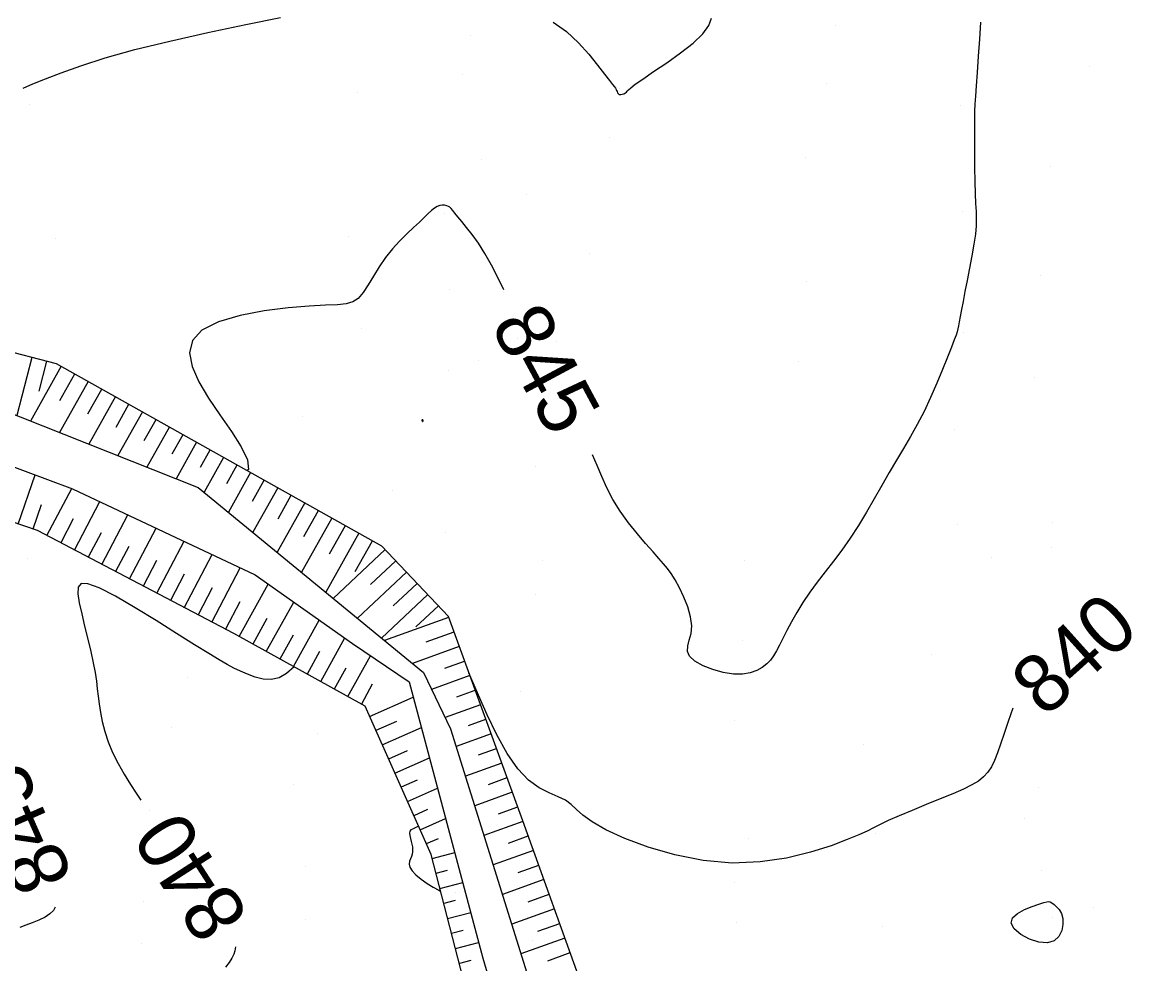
# Model space of a CAD drawing. Extents: x 400243 to 403697, y 4403637 to 4408083.
# Drawn here: x 402954.4 to 403097.6, y 4406092.9 to 4406214.4 of the extents above; entities that cross this region are included whole.
import ezdxf

# ---------------------------------------------------------------- set-up
doc = ezdxf.new("R2010")
doc.units = 0
doc.layers.add('HH_IC', color=7, linetype='Continuous')

msp = doc.modelspace()

# ---------------------------------------------------------------- linework, layer by layer
at = {"layer": 'HH_IC'}
for p, q in [((403059.21, 4406213.91), (403059.21, 4406213.91)), ((403012.14, 4406212.64), (403012.14, 4406212.64)), ((403011.09, 4406207.61), (403011.09, 4406207.61)), ((403091.98, 4406208.73), (403091.98, 4406208.73)), ((403058.04, 4406206.48), (403058.04, 4406206.48)), ((402997.57, 4406205.33), (402997.57, 4406205.33)), ((403031.38, 4406205.84), (403031.38, 4406205.84)), ((402955.34, 4406203.79), (402955.34, 4406203.79)), ((403075.35, 4406203.63), (403075.35, 4406203.63)), ((403030.06, 4406199.58), (403030.06, 4406199.58)), ((403013.63, 4406196.71), (403013.63, 4406196.71)), ((403055.34, 4406196.92), (403055.34, 4406196.92)), ((403086.97, 4406195.81), (403086.97, 4406195.81)), ((403019.34, 4406192.12), (403019.34, 4406192.12)), ((403008.84, 4406189.68), (403008.84, 4406189.68)), ((403075.61, 4406189.94), (403075.61, 4406189.94)), ((402958.69, 4406186.49), (402958.69, 4406186.49)), ((402996.46, 4406186.76), (402996.46, 4406186.76)), ((402958.82, 4406170.35), (402901.3, 4406185)), ((403027.48, 4406184.6), (403027.48, 4406184.6)), ((403055.45, 4406180.9), (403055.45, 4406180.9)), ((403085.71, 4406181.67), (403085.71, 4406181.67)), ((403009.51, 4406179.86), (403009.51, 4406179.86)), ((402998.09, 4406174.95), (402998.09, 4406174.95)), ((403018.25, 4406173.6), (403018.25, 4406173.6)), ((403023.21, 4406173.25), (403023.21, 4406173.25)), ((403075.76, 4406174.36), (403075.76, 4406174.36)), ((402956.35, 4406148.82), (402889, 4406171.92)), ((402956.35, 4406148.82), (402889, 4406171.92)), ((402955.61, 4406171.17), (402953.69, 4406163.65)), ((402956.55, 4406166.79), (402957.54, 4406170.68)), ((402958.82, 4406170.35), (402958.82, 4406170.35)), ((403000.74, 4406146.83), (402958.82, 4406170.35)), ((403013.19, 4406170.82), (403013.19, 4406170.82)), ((403054.42, 4406170.63), (403054.42, 4406170.63)), ((402959.42, 4406170.02), (402955.45, 4406162.95)), ((402959.24, 4406165.62), (402961.16, 4406169.04)), ((403009.28, 4406169.5), (403009.28, 4406169.5)), ((402942.58, 4406168.04), (402977.07, 4406154.39)), ((402962.9, 4406168.06), (402959.2, 4406161.46)), ((403084.9, 4406168.51), (403084.9, 4406168.51)), ((402962.86, 4406163.9), (402964.65, 4406167.08)), ((402966.39, 4406166.1), (402962.96, 4406159.98)), ((402966.48, 4406162.18), (402968.14, 4406165.12)), ((402969.88, 4406164.15), (402966.71, 4406158.49)), ((402970.11, 4406160.46), (402971.63, 4406163.17)), ((402990.48, 4406163.5), (402990.48, 4406163.5)), ((402940.17, 4406161.87), (402960.88, 4406154.21)), ((402973.37, 4406162.19), (402970.46, 4406157.01)), ((403005.99, 4406163.03), (403005.99, 4406163.03)), ((403074.53, 4406161.9), (403074.53, 4406161.9)), ((402973.73, 4406158.74), (402975.11, 4406161.21)), ((402976.86, 4406160.23), (402974.22, 4406155.52)), ((402977.35, 4406157.01), (402978.6, 4406159.25)), ((402980.35, 4406158.27), (402977.82, 4406153.77)), ((402953.87, 4406149.67), (402956.04, 4406156)), ((402980.74, 4406154.89), (402982.09, 4406157.29)), ((402983.83, 4406156.32), (402980.96, 4406151.19)), ((403020.57, 4406157.11), (403020.57, 4406157.11)), ((402984.05, 4406152.62), (402985.58, 4406155.34)), ((402957.57, 4406148.18), (402960.76, 4406154.25)), ((402960.88, 4406154.21), (402960.88, 4406154.21)), ((402960.88, 4406154.21), (402984.42, 4406143.11)), ((402977.07, 4406154.39), (402977.07, 4406154.39)), ((402977.07, 4406154.39), (403006.1, 4406130.54)), ((402987.32, 4406154.36), (402984.1, 4406148.61)), ((402987.37, 4406150.35), (402989.07, 4406153.38)), ((403002.18, 4406154.04), (403002.18, 4406154.04)), ((402956.84, 4406152.16), (402955.76, 4406149.02)), ((402961.11, 4406146.32), (402964.38, 4406152.56)), ((402990.81, 4406152.4), (402987.24, 4406146.03)), ((402960.96, 4406150.33), (402959.34, 4406147.25)), ((402964.65, 4406144.46), (402968.01, 4406150.85)), ((402994.3, 4406150.44), (402990.38, 4406143.45)), ((402990.68, 4406148.08), (402992.56, 4406151.42)), ((402956.35, 4406148.82), (402956.35, 4406148.82)), ((402981.67, 4406135.53), (402956.35, 4406148.82)), ((402981.67, 4406135.53), (402956.35, 4406148.82)), ((402968.19, 4406142.6), (402971.63, 4406149.14)), ((402994, 4406145.81), (402996.04, 4406149.46)), ((403074.91, 4406149.66), (403074.91, 4406149.66)), ((403087.24, 4406149.81), (403087.24, 4406149.81)), ((402964.54, 4406148.55), (402962.88, 4406145.39)), ((402971.74, 4406140.74), (402975.25, 4406147.44)), ((402997.79, 4406148.49), (402993.52, 4406140.87)), ((402997.31, 4406143.55), (402999.53, 4406147.51)), ((403008.98, 4406148.62), (403008.98, 4406148.62)), ((402968.12, 4406146.76), (402966.42, 4406143.53)), ((403001.16, 4406146.38), (402994.49, 4406140.07)), ((403000.74, 4406146.83), (403000.74, 4406146.83)), ((403009.32, 4406137.75), (403000.74, 4406146.83)), ((403087.11, 4406146.64), (403087.11, 4406146.64)), ((402955.02, 4406145.23), (402955.02, 4406145.23)), ((402971.7, 4406144.98), (402969.97, 4406141.67)), ((402975.28, 4406138.88), (402978.87, 4406145.73)), ((402999.29, 4406141.86), (403002.54, 4406144.93)), ((403021.48, 4406144.96), (403021.48, 4406144.96)), ((403047.5, 4406145), (403047.5, 4406145)), ((403079.41, 4406145.35), (403079.41, 4406145.35)), ((402975.28, 4406143.2), (402973.51, 4406139.81)), ((402978.82, 4406137.03), (402982.49, 4406144.03)), ((402984.42, 4406143.11), (402996.98, 4406134.25)), ((402984.42, 4406143.11), (402984.42, 4406143.11)), ((403003.91, 4406143.47), (402997.6, 4406137.52)), ((402982.35, 4406135.15), (402986.1, 4406141.93)), ((403002.22, 4406139.13), (403005.28, 4406142.02)), ((402978.87, 4406141.42), (402977.05, 4406137.95)), ((403006.66, 4406140.57), (403000.72, 4406134.96)), ((403020.62, 4406140.62), (403020.62, 4406140.62)), ((402982.45, 4406139.63), (402980.59, 4406136.1)), ((402985.85, 4406133.22), (402989.39, 4406139.61)), ((403005.15, 4406136.39), (403008.03, 4406139.11)), ((402985.93, 4406137.48), (402984.1, 4406134.18)), ((403009.36, 4406137.63), (403001.11, 4406134.63)), ((403009.32, 4406137.75), (403009.32, 4406137.75)), ((403018.92, 4406111.39), (403009.32, 4406137.75)), ((402989.36, 4406131.28), (402992.68, 4406137.29)), ((402981.67, 4406135.53), (402981.67, 4406135.53)), ((402998.58, 4406126.18), (402981.67, 4406135.53)), ((402998.58, 4406126.18), (402981.67, 4406135.53)), ((402989.32, 4406135.35), (402987.6, 4406132.25)), ((402992.86, 4406129.34), (402995.96, 4406134.97)), ((403006.48, 4406134.46), (403010.05, 4406135.76)), ((403047.3, 4406134.6), (403047.3, 4406134.6)), ((402992.71, 4406133.22), (402991.11, 4406130.31)), ((402996.98, 4406134.25), (402996.98, 4406134.25)), ((402996.98, 4406134.25), (403004.27, 4406129.33)), ((403010.73, 4406133.88), (403004.7, 4406131.68)), ((402979.58, 4406132.81), (402979.58, 4406132.81)), ((402996.36, 4406127.41), (402999.28, 4406132.69)), ((403008.85, 4406131.06), (403011.42, 4406132)), ((403071.63, 4406132.79), (403071.63, 4406132.79)), ((403087.96, 4406131.71), (403087.96, 4406131.71)), ((402996.11, 4406131.1), (402994.61, 4406128.38)), ((403006.1, 4406130.54), (403006.1, 4406130.54)), ((403006.1, 4406130.54), (403009.6, 4406123.27)), ((402975.69, 4406129.9), (402975.69, 4406129.9)), ((402999.52, 4406129.01), (402998.11, 4406126.44)), ((403004.27, 4406129.33), (403004.27, 4406129.33)), ((403004.27, 4406129.33), (403013.77, 4406093.68)), ((403012.1, 4406130.12), (403007.17, 4406128.32)), ((402999.17, 4406124.85), (403004.8, 4406127.35)), ((403010.41, 4406127.37), (403012.78, 4406128.24)), ((403018.63, 4406128.11), (403018.63, 4406128.11)), ((402998.58, 4406126.18), (402998.58, 4406126.18)), ((403007.09, 4406107.04), (402998.58, 4406126.18)), ((403007.09, 4406107.04), (402998.58, 4406126.18)), ((403013.47, 4406126.36), (403008.91, 4406124.7)), ((403011.94, 4406123.67), (403014.15, 4406124.48)), ((402973.61, 4406123.48), (402973.61, 4406123.48)), ((403002.65, 4406124.2), (402999.99, 4406123.02)), ((403000.8, 4406121.19), (403005.84, 4406123.43)), ((403009.6, 4406123.27), (403009.6, 4406123.27)), ((403009.6, 4406123.27), (403027.85, 4406064.92)), ((403046.27, 4406124.34), (403046.27, 4406124.34)), ((402992.49, 4406122.71), (402992.49, 4406122.71)), ((403014.84, 4406122.6), (403010.33, 4406120.96)), ((403003.99, 4406120.42), (403001.61, 4406119.36)), ((403013.22, 4406119.88), (403015.52, 4406120.72)), ((403062.88, 4406121.21), (403062.88, 4406121.21)), ((403002.42, 4406117.54), (403006.88, 4406119.52)), ((403016.2, 4406118.84), (403011.52, 4406117.14)), ((403017.49, 4406119.36), (403017.49, 4406119.36)), ((402989.42, 4406116.11), (402989.42, 4406116.11)), ((403005.32, 4406116.64), (403003.23, 4406115.71)), ((403014.5, 4406116.09), (403016.89, 4406116.96)), ((403004.05, 4406113.88), (403007.93, 4406115.61)), ((403017.57, 4406115.08), (403012.72, 4406113.31)), ((403085.42, 4406115.72), (403085.42, 4406115.72)), ((403015.79, 4406112.3), (403018.26, 4406113.2)), ((402970.84, 4406112.78), (402970.84, 4406112.78)), ((403006.65, 4406112.85), (403004.86, 4406112.05)), ((403005.67, 4406110.23), (403008.97, 4406111.69)), ((403083.63, 4406111.64), (403083.63, 4406111.64)), ((403018.94, 4406111.32), (403013.91, 4406109.51)), ((403018.92, 4406111.39), (403018.92, 4406111.39)), ((403041.29, 4406049.22), (403018.92, 4406111.39)), ((403007.99, 4406109.07), (403006.48, 4406108.4)), ((403017.06, 4406108.52), (403019.62, 4406109.44)), ((403048, 4406109.06), (403048, 4406109.06)), ((403064.38, 4406109.81), (403064.38, 4406109.81)), ((403007.22, 4406106.54), (403010.14, 4406107.3)), ((403020.3, 4406107.56), (403015.1, 4406105.69)), ((403007.09, 4406107.04), (403007.09, 4406107.04)), ((403014.12, 4406079.97), (403007.09, 4406107.04)), ((403014.12, 4406079.97), (403007.09, 4406107.04)), ((402990.86, 4406105.5), (402990.86, 4406105.5)), ((403009.19, 4406104.99), (403007.72, 4406104.61)), ((403018.33, 4406104.73), (403020.97, 4406105.68)), ((403085.76, 4406104.98), (403085.76, 4406104.98)), ((403008.22, 4406102.67), (403011.17, 4406103.44)), ((403021.65, 4406103.8), (403016.29, 4406101.87)), ((403046.28, 4406103.46), (403046.28, 4406103.46)), ((403010.24, 4406102.17), (403010.24, 4406102.17)), ((403019.61, 4406100.94), (403022.33, 4406101.91)), ((402969.98, 4406101), (402969.98, 4406101)), ((403010.21, 4406101.12), (403008.73, 4406100.74)), ((403092.52, 4406100.25), (403092.52, 4406100.25)), ((403009.23, 4406098.8), (403012.2, 4406099.57)), ((403023, 4406100.03), (403017.49, 4406098.05)), ((403087.23, 4406098.97), (403087.23, 4406098.97)), ((402990.84, 4406098.61), (402990.84, 4406098.61)), ((403011.23, 4406097.25), (403009.73, 4406096.86)), ((403020.88, 4406097.14), (403023.68, 4406098.15)), ((403046.46, 4406098.33), (403046.46, 4406098.33)), ((403065.29, 4406097.75), (403065.29, 4406097.75)), ((403024.36, 4406096.27), (403018.68, 4406094.23)), ((403020.18, 4406095.96), (403020.18, 4406095.96)), ((402969.76, 4406095.6), (402969.76, 4406095.6)), ((403010.24, 4406094.93), (403013.23, 4406095.71)), ((403022.16, 4406093.35), (403025.04, 4406094.39)), ((403012.24, 4406093.38), (403010.74, 4406092.99)), ((403013.77, 4406093.68), (403013.77, 4406093.68)), ((403013.77, 4406093.68), (403017.01, 4406082.7))]:
    msp.add_line(p, q, dxfattribs=at)
for points in [[(402954.48, 4406205.91), (402955.76, 4406206.43), (402957.37, 4406207.09), (402959.39, 4406207.89), (402961.93, 4406208.79), (402965.06, 4406209.79), (402968.88, 4406210.86), (402973.4, 4406211.97), (402978.3, 4406213.06), (402983.19, 4406214.09), (402987.69, 4406215)], [(403022.83, 4406214.41), (403024.56, 4406213.18), (403026.11, 4406211.75), (403027.45, 4406210.26), (403028.57, 4406208.87), (403029.45, 4406207.71), (403030.08, 4406206.89), (403030.49, 4406206.36), (403030.74, 4406206.05), (403030.88, 4406205.87), (403030.96, 4406205.74), (403031.02, 4406205.6), (403031.08, 4406205.44), (403031.15, 4406205.29), (403031.24, 4406205.17), (403031.38, 4406205.09), (403031.55, 4406205.08), (403031.75, 4406205.11), (403031.96, 4406205.18), (403032.15, 4406205.28), (403032.29, 4406205.38), (403032.39, 4406205.49), (403032.53, 4406205.66), (403032.84, 4406205.93), (403033.42, 4406206.39), (403034.38, 4406207.07), (403035.79, 4406208.02), (403037.49, 4406209.17), (403039.25, 4406210.43), (403040.88, 4406211.71), (403042.14, 4406212.91), (403042.9, 4406213.98), (403043.23, 4406214.91)], [(403077.95, 4406214.4), (403077.81, 4406212.2), (403077.65, 4406210), (403077.5, 4406207.93), (403077.38, 4406206.19), (403077.28, 4406204.85), (403077.22, 4406203.82), (403077.17, 4406202.92), (403077.15, 4406201.96), (403077.14, 4406200.78), (403077.14, 4406199.26), (403077.14, 4406197.5), (403077.16, 4406195.64), (403077.19, 4406193.85), (403077.23, 4406192.27), (403077.3, 4406191.01), (403077.36, 4406189.99), (403077.39, 4406189.08), (403077.37, 4406188.15), (403077.28, 4406187.07), (403077.09, 4406185.75), (403076.83, 4406184.25), (403076.53, 4406182.67), (403076.22, 4406181.1), (403075.93, 4406179.65), (403075.69, 4406178.39), (403075.49, 4406177.33), (403075.33, 4406176.46), (403075.2, 4406175.76), (403075.1, 4406175.23), (403075.02, 4406174.83), (403074.93, 4406174.47), (403074.79, 4406174.03), (403074.55, 4406173.41), (403074.2, 4406172.5), (403073.69, 4406171.21), (403073.05, 4406169.62), (403072.31, 4406167.85), (403071.5, 4406166.01), (403070.65, 4406164.2), (403069.78, 4406162.52), (403068.91, 4406160.95), (403068.01, 4406159.42), (403067.1, 4406157.89), (403066.17, 4406156.31), (403065.22, 4406154.64), (403064.24, 4406152.92), (403063.23, 4406151.18), (403062.2, 4406149.47), (403061.14, 4406147.83), (403060.06, 4406146.31), (403058.97, 4406144.88), (403057.9, 4406143.51), (403056.88, 4406142.19), (403055.92, 4406140.88), (403055.04, 4406139.57), (403054.26, 4406138.28), (403053.56, 4406137.05), (403052.95, 4406135.92), (403052.44, 4406134.9), (403052.01, 4406134.04), (403051.63, 4406133.31), (403051.26, 4406132.68), (403050.86, 4406132.13), (403050.38, 4406131.64), (403049.8, 4406131.18), (403049.08, 4406130.78), (403048.23, 4406130.48), (403047.23, 4406130.31), (403046.08, 4406130.32), (403044.77, 4406130.53), (403043.43, 4406130.9), (403042.17, 4406131.4), (403041.12, 4406131.98), (403040.42, 4406132.61), (403040.14, 4406133.25), (403040.18, 4406133.94), (403040.38, 4406134.69), (403040.61, 4406135.55), (403040.7, 4406136.56), (403040.55, 4406137.72), (403040.19, 4406138.98), (403039.69, 4406140.24), (403039.12, 4406141.43), (403038.56, 4406142.46), (403038.06, 4406143.27), (403037.59, 4406143.93), (403037.07, 4406144.55), (403036.47, 4406145.23), (403035.71, 4406146.07), (403034.76, 4406147.14), (403033.69, 4406148.42), (403032.57, 4406149.83), (403031.49, 4406151.33), (403030.53, 4406152.84), (403029.76, 4406154.33), (403029.11, 4406155.78), (403028.52, 4406157.21), (403027.92, 4406158.61)], [(403016.48, 4406179.9), (403015.71, 4406181.48), (403014.88, 4406183.08), (403014.04, 4406184.58), (403013.2, 4406185.89), (403012.4, 4406187.01), (403011.68, 4406187.94), (403011.04, 4406188.71), (403010.53, 4406189.31), (403010.15, 4406189.77), (403009.89, 4406190.11), (403009.69, 4406190.35), (403009.52, 4406190.52), (403009.33, 4406190.64), (403009.11, 4406190.73), (403008.84, 4406190.79), (403008.54, 4406190.81), (403008.21, 4406190.76), (403007.88, 4406190.63), (403007.54, 4406190.42), (403007.17, 4406190.11), (403006.74, 4406189.71), (403006.22, 4406189.21), (403005.59, 4406188.61), (403004.82, 4406187.9), (403003.95, 4406187.09), (403003.03, 4406186.17), (403002.11, 4406185.16), (403001.22, 4406184.05), (403000.42, 4406182.86), (402999.68, 4406181.65), (402999, 4406180.52), (402998.34, 4406179.53), (402997.68, 4406178.78), (402997, 4406178.31), (402996.16, 4406178.07), (402995.04, 4406177.96), (402993.5, 4406177.9), (402991.39, 4406177.79), (402988.66, 4406177.56), (402985.57, 4406177.16), (402982.46, 4406176.57), (402979.67, 4406175.76), (402977.54, 4406174.69), (402976.32, 4406173.35), (402975.95, 4406171.77), (402976.27, 4406169.98), (402977.13, 4406168.02), (402978.38, 4406165.92), (402979.86, 4406163.74), (402981.35, 4406161.6), (402982.62, 4406159.62), (402983.43, 4406157.95), (402983.56, 4406156.72), (402983.4, 4406156.56)], [(403006.07, 4406162.99), (403006.07, 4406163.01), (403006.06, 4406163.03), (403006.06, 4406163.05), (403006.05, 4406163.06), (403006.04, 4406163.07), (403006.04, 4406163.08), (403006.03, 4406163.09), (403006.02, 4406163.09), (403006.02, 4406163.09), (403006.01, 4406163.1), (403006, 4406163.1), (403005.99, 4406163.1), (403005.97, 4406163.1), (403005.96, 4406163.1), (403005.94, 4406163.09), (403005.93, 4406163.09), (403005.92, 4406163.08), (403005.91, 4406163.06), (403005.9, 4406163.05), (403005.9, 4406163.04), (403005.9, 4406163.02), (403005.91, 4406163), (403005.92, 4406162.99), (403005.94, 4406162.97), (403005.95, 4406162.96), (403005.97, 4406162.94), (403005.98, 4406162.93), (403005.99, 4406162.92), (403006, 4406162.91), (403006.01, 4406162.9), (403006.01, 4406162.9), (403006.02, 4406162.9), (403006.02, 4406162.9), (403006.02, 4406162.9), (403006.03, 4406162.91), (403006.04, 4406162.92), (403006.05, 4406162.94), (403006.06, 4406162.95), (403006.06, 4406162.97), (403006.07, 4406162.99)], [(402989.45, 4406131.23), (402988.46, 4406130.37), (402987.49, 4406129.83), (402986.48, 4406129.62), (402985.44, 4406129.67), (402984.42, 4406129.92), (402983.43, 4406130.29), (402982.52, 4406130.7), (402981.68, 4406131.1), (402980.81, 4406131.55), (402979.77, 4406132.14), (402978.42, 4406132.95), (402976.61, 4406134.07), (402974.29, 4406135.54), (402971.64, 4406137.21), (402968.92, 4406138.88), (402966.39, 4406140.36), (402964.3, 4406141.44), (402962.86, 4406141.97), (402962, 4406141.98), (402961.61, 4406141.52), (402961.56, 4406140.68), (402961.74, 4406139.5), (402962.05, 4406138.08), (402962.42, 4406136.49), (402962.82, 4406134.84), (402963.21, 4406133.23), (402963.53, 4406131.76), (402963.77, 4406130.5), (402963.94, 4406129.41), (402964.06, 4406128.42), (402964.17, 4406127.46), (402964.3, 4406126.46), (402964.47, 4406125.37), (402964.7, 4406124.19), (402965.03, 4406122.92), (402965.46, 4406121.59), (402966.03, 4406120.2), (402966.74, 4406118.78), (402967.53, 4406117.39), (402968.34, 4406116.09), (402969.08, 4406114.95), (402969.69, 4406114.04)], [(403082.12, 4406125.91), (403081.52, 4406124.22), (403080.98, 4406122.65), (403080.52, 4406121.29), (403080.12, 4406120.14), (403079.73, 4406119.16), (403079.33, 4406118.34), (403078.88, 4406117.65), (403078.34, 4406117.05), (403077.66, 4406116.52), (403076.8, 4406116.01), (403075.72, 4406115.48), (403074.37, 4406114.89), (403072.73, 4406114.21), (403070.94, 4406113.48), (403069.12, 4406112.74), (403067.43, 4406112.04), (403066.02, 4406111.43), (403064.98, 4406110.93), (403064.14, 4406110.5), (403063.31, 4406110.07), (403062.25, 4406109.58), (403060.75, 4406108.96), (403058.66, 4406108.17), (403056.01, 4406107.33), (403052.94, 4406106.59), (403049.53, 4406106.08), (403045.91, 4406105.94), (403042.18, 4406106.28), (403038.51, 4406107.01), (403035.08, 4406108), (403032.06, 4406109.12), (403029.62, 4406110.23), (403027.87, 4406111.24), (403026.67, 4406112.12), (403025.83, 4406112.87), (403025.14, 4406113.51), (403024.41, 4406114.04), (403023.46, 4406114.49), (403022.32, 4406114.98), (403021.04, 4406115.64), (403019.67, 4406116.63), (403018.27, 4406118.09), (403016.89, 4406120.09), (403015.56, 4406122.49), (403014.32, 4406125.06), (403013.2, 4406127.59), (403012.23, 4406129.86), (403011.97, 4406130.46)], [(403005.47, 4406110.68), (403004.95, 4406110.42), (403004.69, 4406110.32), (403004.49, 4406110.21), (403004.35, 4406110.04), (403004.31, 4406109.79), (403004.34, 4406109.48), (403004.42, 4406109.12), (403004.52, 4406108.74), (403004.61, 4406108.37), (403004.68, 4406108.02), (403004.71, 4406107.7), (403004.7, 4406107.39), (403004.65, 4406107.09), (403004.56, 4406106.8), (403004.43, 4406106.49), (403004.32, 4406106.17), (403004.28, 4406105.81), (403004.37, 4406105.41), (403004.64, 4406104.95), (403005.14, 4406104.42), (403005.81, 4406103.87), (403006.57, 4406103.32), (403007.35, 4406102.83), (403008.08, 4406102.43), (403008.31, 4406102.32)], [(402958.64, 4406100.23), (402958.4, 4406099.8), (402957.96, 4406099.39), (402957.32, 4406098.98), (402956.53, 4406098.59), (402955.68, 4406098.23), (402954.84, 4406097.91), (402954.09, 4406097.63)], [(403088.53, 4406098.8), (403088.56, 4406098.03), (403088.4, 4406097.22), (403088.03, 4406096.47), (403087.43, 4406095.91), (403086.58, 4406095.64), (403085.47, 4406095.73), (403084.26, 4406096.13), (403083.14, 4406096.73), (403082.29, 4406097.45), (403081.89, 4406098.19), (403082.08, 4406098.86), (403082.72, 4406099.44), (403083.62, 4406099.93), (403084.6, 4406100.33), (403085.47, 4406100.64), (403086.08, 4406100.84), (403086.47, 4406100.95), (403086.73, 4406100.98), (403086.92, 4406100.92), (403087.13, 4406100.79), (403087.42, 4406100.59), (403087.75, 4406100.31), (403088.08, 4406099.93), (403088.36, 4406099.43), (403088.53, 4406098.8)], [(402981.88, 4406095.12), (402981.8, 4406094.64), (402981.65, 4406094.17), (402981.4, 4406093.66), (402981.04, 4406093.11), (402980.57, 4406092.51)]]:
    msp.add_lwpolyline(points, dxfattribs=at)

# ---------------------------------------------------------------- texts
for s, rotation, p in [('845', 298.2471, (403014.68, 4406175.32)), ('840', 41.9208, (403086.25, 4406124.57)), ('845', 113.7908, (402961.01, 4406104.16)), ('840', 122.7862, (402983.76, 4406099.12))]:
    msp.add_text(s, height=7.5, rotation=rotation, dxfattribs=at).set_placement(p)

doc.saveas('drawing.dxf')
